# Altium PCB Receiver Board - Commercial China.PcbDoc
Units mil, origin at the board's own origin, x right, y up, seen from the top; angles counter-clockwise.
Board outline 2000 x 1000 mil, 2 copper layers (Top Layer, Bottom Layer); 23 components, 21 nets, 121 pads, 26 vias.
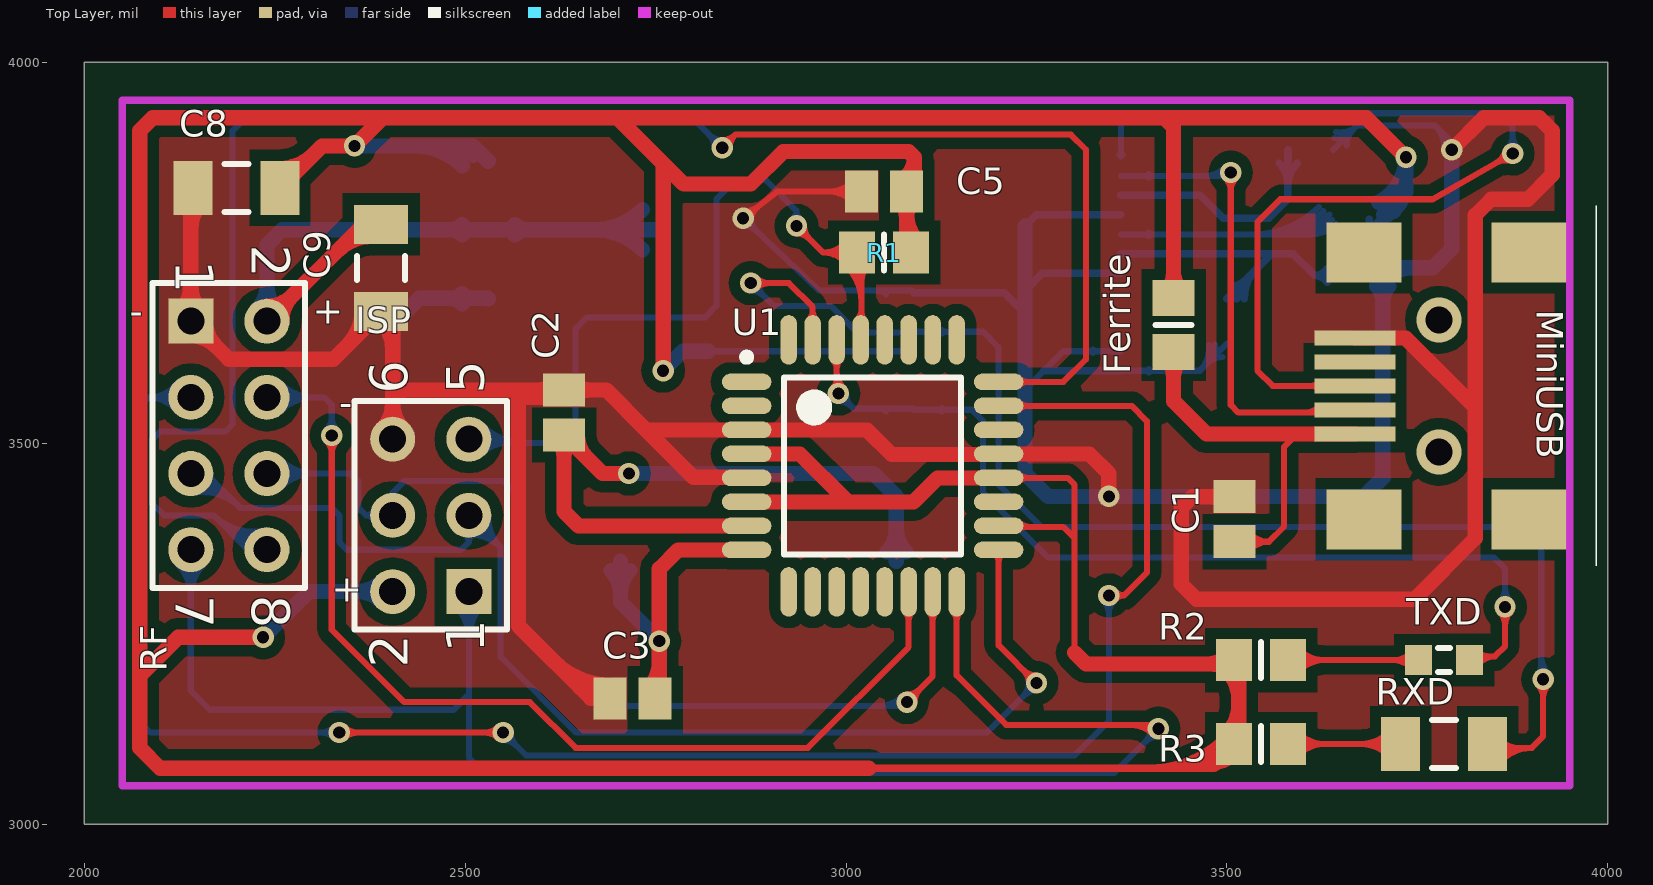
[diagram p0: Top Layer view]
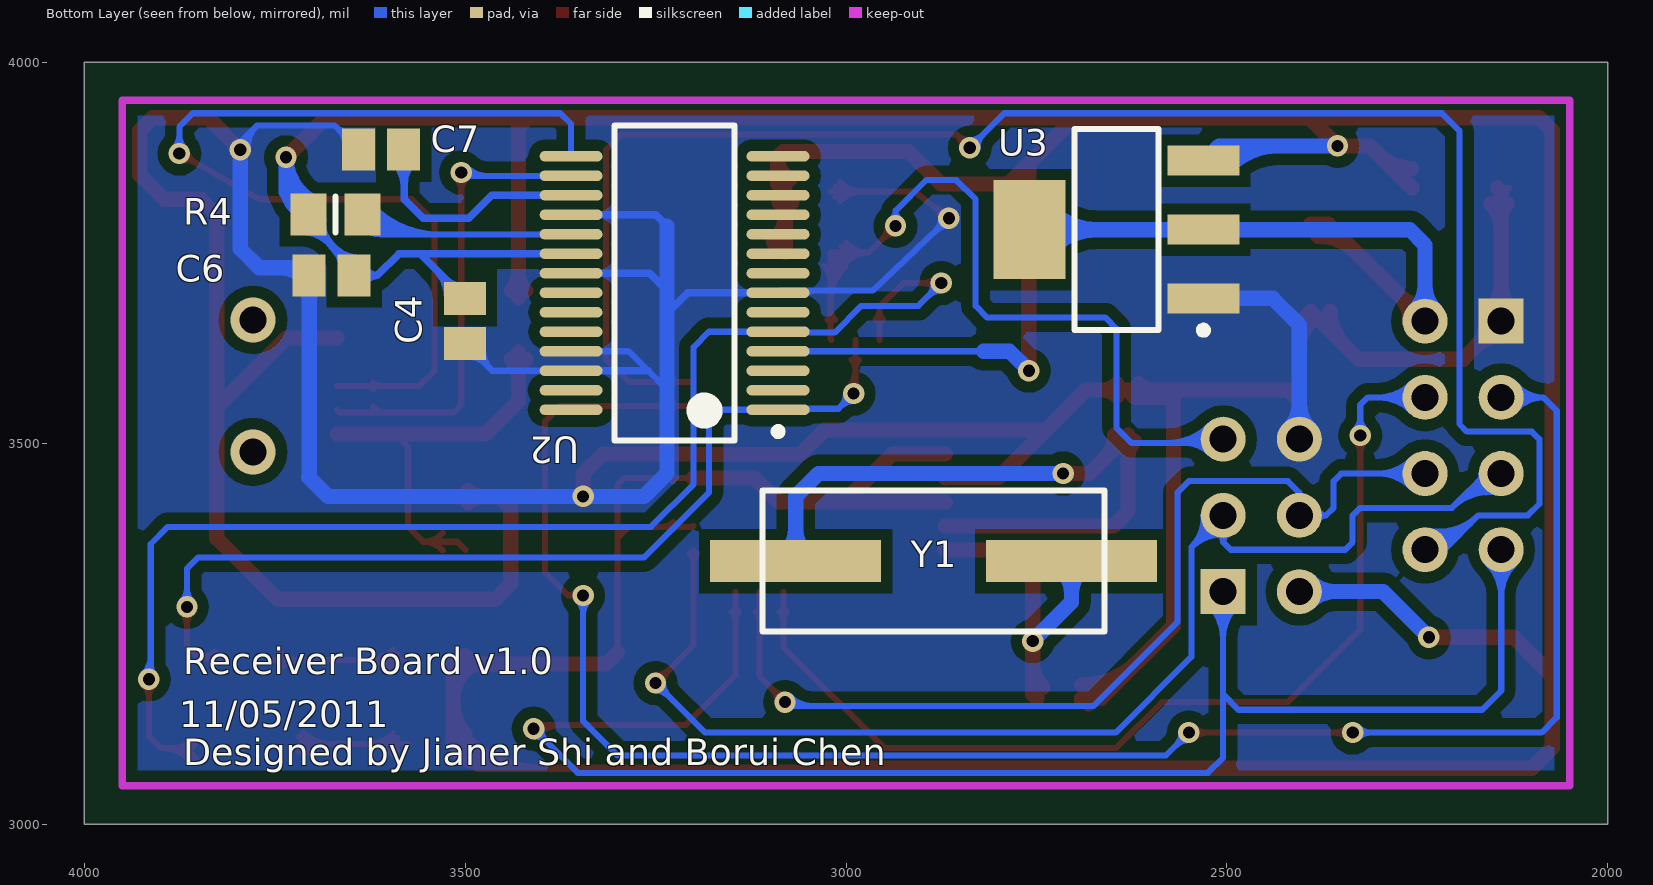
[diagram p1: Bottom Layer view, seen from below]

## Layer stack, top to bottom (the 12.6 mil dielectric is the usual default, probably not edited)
Top Layer: signal copper 1.4
Dielectric: dielectric 12.6, FR-4, Dk 4.8
Bottom Layer: signal copper 1.4

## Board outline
2000,3000 4000,3000 4000,4000 2000,4000

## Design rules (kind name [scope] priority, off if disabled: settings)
Clearance "Polygon Clearance" [InPolygon] p1: gap=15
Clearance [All] p2: gap=8.1
HoleSize [All] p1: absolutevalues=TRUE maxlimit=100 minlimit=16 maxpercent=80.000 minpercent=20.000
MinimumAnnularRing [All] p1: minimumring=6
PolygonConnect [All] p1: connectstyle=Direct reliefconductorwidth=10 reliefentries=4 polygonreliefangle="90 Angle"
RoutingVias [All] p1: holewidth=16 width=28 viastyle="Through Hole" minholewidth=16 minwidth=27 maxholewidth=16 maxwidth=35
SilkscreenOverComponentPads [All] p1: minsilkscreentomaskgap=10
SolderMaskExpansion [All] p1: expansion=4
Width [All] p1: maxlimit=50 minlimit=8 preferedwidth=8
26 further rules are at their usual default settings.

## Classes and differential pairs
component class "5V to 3.3V": C8 C9 U3
component class "2.4ghz Receiver Board": C1 C2 C3 C4 C5 C6 C7 Ferrite ISP MiniUSB R1 R2 R3 R4 RF RXD TXD U1 U2 Y1

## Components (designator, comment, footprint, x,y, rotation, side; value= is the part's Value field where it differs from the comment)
C1 "Cap Semi" CAPC2012L 3510,3400 r90 top
C2 "Cap Semi" CAPC2012L 2630,3540 r270 top
C3 "Cap Semi" CAPC2012L 2720,3165 r0 top
C4 "Cap Semi" CAPC2012L 3500,3660 r90 bottom
C5 "Cap Semi" CAPC2012L 3050,3830 r0 top
C6 "Cap Semi" CAPC2012L 3675,3720 r180 bottom
C7 "Cap Semi" CAPC2012L 3610,3885 r0 bottom
C8 "Cap Pol3 TANT" capc3216n 2200,3835 r180 top
C9 "Cap Pol3 TANT" capc3216n 2390,3730 r270 top
Ferrite "Ferrite Bead 1A" RESC2012N 3430,3655 r90 top
ISP "Header 3X2" HDR2X3 2505,3305 r90 top
MiniUSB "Mini USB" "MINI USB" 3985,3575 r180 top
R1 "Res3" RESC2012N 3050,3750 r0 top
R2 "Res3" RESC2012N 3545,3215 r0 top
R3 "Res3" RESC2012N 3545,3105 r0 top
R4 "Res3" RESC2012N 3670,3800 r180 bottom
RF "Header 4X2" HDR2X4 2140,3660 r270 top (schematic designator "RF Board")
RXD "LED2" RESC3216N 3785,3105 r0 top
TXD "LED2" RESC1608N 3785,3215 r0 top
U1 "ATmega8L-8AI" 32A_N 3035,3470 r0 top
U2 "FT232RL-Reel" SSOP-28_N 3225,3710 r0 bottom
U3 "LM1117MPX-3.3" MP04A_N 2645,3780 r0 bottom
Y1 "XTAL 8Mhz" "HC-49U - SMD" 2885,3345 r180 bottom

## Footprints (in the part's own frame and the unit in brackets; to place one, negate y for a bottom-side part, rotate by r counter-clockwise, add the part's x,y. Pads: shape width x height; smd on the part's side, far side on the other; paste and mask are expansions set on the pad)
32A_N [mm] "Thin QFP, 32-Leads, Body 7x7mm, Pitch 0.8mm, IPC Medium Density"
  oval 1.65x0.55 smd: 1(-4.2,2.8) 2(-4.2,2) 3(-4.2,1.2) 4(-4.2,0.4) 5(-4.2,-0.4) 6(-4.2,-1.2) 7(-4.2,-2) 8(-4.2,-2.8) 17(4.2,-2.8) 18(4.2,-2) 19(4.2,-1.2) 20(4.2,-0.4) 21(4.2,0.4) 22(4.2,1.2) 23(4.2,2) 24(4.2,2.8)
  oval 0.55x1.65 smd: 9(-2.8,-4.2) 10(-2,-4.2) 11(-1.2,-4.2) 12(-0.4,-4.2) 13(0.4,-4.2) 14(1.2,-4.2) 15(2,-4.2) 16(2.8,-4.2) 25(2.8,4.2) 26(2,4.2) 27(1.2,4.2) 28(0.4,4.2) 29(-0.4,4.2) 30(-1.2,4.2) 31(-2,4.2) 32(-2.8,4.2)
  silkscreen extent -4.32,-2.95 2.95,3.75, body extent -3.5,-3.5 3.5,3.5, height 1.2
CAPC2012L [mm] "Chip Capacitor, Body 2.0x1.3mm, IPC High Density"
  rect 1.1x1.4 smd: 1(-0.75,0) 2(0.75,0)
  body extent -1.1,-0.72 1.1,0.72, height 1.1
capc3216n [mm] "Chip Capacitor, Body 3.2x1.6mm, IPC Medium Density"
  rect 1.3x1.8 smd: 1(-1.45,0) 2(1.45,0)
  silkscreen extent -0.4,-0.8 0.4,0.8, body extent -1.7,-0.9 1.7,0.9, height 1.35
"HC-49U - SMD" [mm] "Quartz Crystal, Thru-Hole; 2 Leads; Body 11.35 x 4.65 x 13.46 mm (LxWxH max)"
  rect 5.7x1.4 smd: 1(-4.6,0) 2(4.6,0)
  silkscreen extent -5.7,-2.35 5.7,2.35
HDR2X3 [mm] "Connector; Header; 3x2 Position"
  rect 1.5x1.5 hole 0.9: 1(0,0)
  round 1.5 hole 0.9: 2(0,2.54) 3(2.54,0) 4(2.54,2.54) 5(5.08,0) 6(5.08,2.54)
  silkscreen extent -1.27,-1.27 6.35,3.81
HDR2X4 [mm] "Connector; Header; 4x2 Position"
  rect 1.5x1.5 hole 0.9: 1(0,0)
  round 1.5 hole 0.9: 2(0,2.54) 3(2.54,0) 4(2.54,2.54) 5(5.08,0) 6(5.08,2.54) 7(7.62,0) 8(7.62,2.54)
  silkscreen extent -1.27,-1.27 8.89,3.81
"MINI USB" [mm] "Digikey http://search.digikey.com/us/en/products/1734035-2/A31727CT-ND/773789"
  rect 2.7x0.5 smd: 1(8.05,1.6) 2(8.05,0.8) 3(8.05,0) 4(8.05,-0.8) 5(8.05,-1.6)
  rect 2.5x2 smd: NC(2.25,4.45) NC(2.25,-4.45) NC(7.75,-4.45) NC(7.75,4.45)
  silkscreen extent 0,-6 0,6
MP04A_N [mm] "SOT223, 4-Leads, Body 6.5x3.5mm, Pitch 2.3mm, Lead Span 7mm, IPC Medium Density"
  rect 2.4x1 smd: 1(-2.9,2.3) 2(-2.9,0) 3(-2.9,-2.3)
  rect 2.4x3.3 smd: 4(2.9,0)
  silkscreen extent -3.02,-3.35 1.4,3.47, body extent -1.85,-3.35 1.85,3.35, height 1.8
RESC1608N [mm] "Chip Resistor, Body 1.6x0.8mm, IPC Medium Density"
  rect 0.9x1 smd: 1(-0.85,0) 2(0.85,0)
  silkscreen extent -0.2,-0.4 0.2,0.4, body extent -0.85,-0.48 0.85,0.48, height 0.6
RESC2012N [mm] "Chip Resistor, Body 2.0x1.3mm, IPC Medium Density"
  rect 1.2x1.4 smd: 1(-0.9,0) 2(0.9,0)
  silkscreen extent 0,-0.6 0,0.6, body extent -1.07,-0.7 1.07,0.7, height 0.65
RESC3216N [mm] "Chip Resistor, Body 3.2x1.6mm, IPC Medium Density"
  rect 1.3x1.8 smd: 1(-1.45,0) 2(1.45,0)
  silkscreen extent -0.4,-0.8 0.4,0.8, body extent -1.68,-0.87 1.68,0.87, height 0.71
SSOP-28_N [mm] "SOP, 28-Leads, Body 10.2x5.3mm, Pitch 0.65mm, IPC Medium Density"
  oval 2.1x0.35 smd: 1(-3.45,4.225) 2(-3.45,3.575) 3(-3.45,2.925) 4(-3.45,2.275) 5(-3.45,1.625) 6(-3.45,0.975) 7(-3.45,0.325) 8(-3.45,-0.325) 9(-3.45,-0.975) 10(-3.45,-1.625) 11(-3.45,-2.275) 12(-3.45,-2.925) 13(-3.45,-3.575) 14(-3.45,-4.225) 15(3.45,-4.225) 16(3.45,-3.575) 17(3.45,-2.925) 18(3.45,-2.275) 19(3.45,-1.625) 20(3.45,-0.975) 21(3.45,-0.325) 22(3.45,0.325) 23(3.45,0.975) 24(3.45,1.625) 25(3.45,2.275) 26(3.45,2.925) 27(3.45,3.575) 28(3.45,4.225)
  silkscreen extent -3.57,-5.25 2,5.25, body extent -2.8,-5.25 2.8,5.25, height 2

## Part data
C1 C2 C3 C4 C5 C6 C7: "Capacitor (Semiconductor SIM Model)"
C8 C9: library part "Cap Pol3", "Polarized Capacitor (Surface Mount)"
Ferrite: library part "Ferrite Bead"
ISP: "Header, 3-Pin, Dual row"
R1 R2 R3 R4: "Resistor"
RF: "Header, 4-Pin, Dual row"
RXD TXD: "Typical RED, GREEN, YELLOW, AMBER GaAs LED"
U1: "8-Bit AVR Microcontroller with 8K Bytes of In-System Programmable Flash Memory"
U2: "USB UART Asynchronous Serial Data Transfer Chip, SSOP-28, Tape and Reel"
U3: "800mA Low-Dropout Linear Regulator, 4-pin SOT-223"
Y1: library part XTAL, "Crystal Oscillator"

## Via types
v1: diameter 28, hole 16, Top Layer to Bottom Layer, 24 vias
v2: diameter 59.06, hole 35.43, Top Layer to Bottom Layer, 2 vias

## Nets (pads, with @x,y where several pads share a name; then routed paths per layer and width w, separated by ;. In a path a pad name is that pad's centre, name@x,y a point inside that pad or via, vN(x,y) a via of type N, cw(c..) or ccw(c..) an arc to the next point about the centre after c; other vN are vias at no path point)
3.3VCC: C9.1 RF.2 U3.2 U3.4 | length 1247.2
  Top Layer w20: RF.2 2367.09,3787.09 C9.1 ; RF.2@2240,3679.53 ccw(c2240,3726.67) 2273.34,3693.34 ccw(c2306.67,3660) RF.2@2259.53,3660 ; 2331.23,3751.23 cw(c2380.16,3702.3) C9.1@2380.16,3771.5
  Bottom Layer w20: RF.2@2226.19,3673.81 ccw(c2192.86,3707.14) 2240,3707.14 ccw(c2287.14,3707.14) RF.2@2253.81,3673.81 ; RF.2 2240,3760 2260,3780 U3.2 U3.4 ; U3.2@2496.42,3773.15 ccw(c2479.89,3756.62) 2479.89,3780 ccw(c2479.89,3803.38) U3.2@2496.42,3786.85 ; U3.2@2565.23,3773.15 cw(c2581.77,3756.62) 2581.77,3780 cw(c2581.77,3803.38) U3.2@2565.23,3786.85 ; U3.4@2732.84,3753.66 ccw(c2669.26,3690.08) 2669.26,3780 ccw(c2669.26,3869.92) U3.4@2732.84,3806.34
5VCC: C4.2 C5.2 C6.2 C8.1 Ferrite.2 ISP.2 R1.2 R2.1 R3.1 R4.1 U1.4 U1.6 U1.18 U1.20 U2.4 U2.20 U3.3 | length 9447.2
  Top Layer w8: U1.18 3201.61,3390 3285,3390 3300,3375 ; U1.20 3290.75,3454.25 3300,3445 3300,3375 ; U1.18@3226.84,3386.43 cw(c3235.45,3377.82) 3235.45,3390 ; U1.18@3226.84,3396.09 ccw(c3241.53,3410.78) 3241.53,3390 ; U1.20@3226.84,3449.42 cw(c3238.49,3437.77) 3238.49,3454.25 cw(c3238.49,3470.73) U1.20@3226.84,3459.08 ; 3300,3225 3300,3375 ; R2.1@3510.47,3210 R2.1@3515.47,3215
  Top Layer w10: 3030,3073.1 3483.57,3073.1 ; 3345,3926.9 3350,3931.9 ; 3397.1,3073.1 ccw(c3397.1,3213.53) R3.1@3496.4,3114.23 ; 3421.24,3073.1 ccw(c3421.24,3189.39) R3.1@3503.47,3107.16 ; 3445.38,3073.1 ccw(c3445.38,3165.25) R3.1@3510.54,3100.09 ; 3469.53,3073.1 ccw(c3469.53,3141.1) R3.1@3517.61,3093.02 ; R3.1@3491.25,3097.71 cw(c3463.95,3092.72) 3483.57,3073.1 ; R3.1@3508.39,3082.48 ccw(c3506.37,3050.31) 3483.57,3073.1 ; R3.1@3515.47,3105 3483.57,3073.1
  Top Layer w20: v1(2235,3245) 2123.1,3245 2073.1,3195 ; C8.1 2312.09,3890 v1(2355,3890) 2391.9,3926.9 ; C8.1@2257.09,3860.43 ccw(c2257.09,3921.83) 2300.5,3878.42 ; v1(2760,3595) 2760,3866.9 ; U1.6 3088.5,3422.76 3120,3454.25 U1.20 ; U1.4 2939.25,3485.75 3000,3425 ; 3030,3073.1 2100,3073.1 2073.1,3100 2073.1,3195 ; C5.2@3071.29,3815.85 cw(c3051.39,3795.96) 3079.53,3795.96 cw(c3107.66,3795.96) C5.2@3087.77,3815.85 ; C5.2@3073.53,3845.9 ccw(c3056.05,3875) 3090,3875 ; R1.2@3079.53,3750 C5.2 3090,3840.47 3090,3875 ; 3079.53,3801.08 ccw(c3132.58,3801.08) R1.2@3095.07,3763.57 ; 3300,3225 3315,3210 R2.1@3510.47,3210 ; Ferrite.2@3420.37,3700.07 ccw(c3397.11,3723.32) 3430,3723.32 ccw(c3462.89,3723.32) Ferrite.2@3439.63,3700.07 ; Ferrite.2 3430,3875 3430,3915 3418.1,3926.9 ; 3474.11,3210 ccw(c3474.11,3246.52) R2.1@3499.93,3220.7 ; 3479.25,3210 cw(c3479.25,3180.74) 3499.93,3201.43 cw(c3462.42,3163.92) 3515.47,3163.92 ; R3.1@3499.93,3118.57 ccw(c3462.42,3156.08) 3515.47,3156.08 ; R3.1@3515.47,3105 R2.1@3515.47,3215 ; v1(3735,3875) 3683.1,3926.9 3418.1,3926.9 ; 2073.1,3195 2073.1,3910 2090,3926.9 2391.9,3926.9 ; 2391.9,3926.9 2700,3926.9 ; 2700,3926.9 2760,3866.9 ; 2700,3926.9 3345,3926.9 3418.1,3926.9 ; 2760,3866.9 2786.9,3840 2875,3840 2917.7,3882.7 3082.3,3882.7 3090,3875
  Bottom Layer w8: 2819.57,3620.43 U2.4 ; U2.4@3052.68,3618.39 ccw(c3047.75,3613.46) 3047.75,3620.43 ccw(c3047.75,3627.41) U2.4@3052.68,3622.48
  Bottom Layer w10: U2.20 3558.86,3748.39 ; C4.2 3558.86,3748.39 ; C4.2@3505.91,3706.18 ccw(c3505.91,3732.13) 3524.25,3713.78 ; C4.2@3512.56,3689.53 cw(c3542.88,3689.53) C4.2@3521.44,3710.97 ; C4.2@3522.56,3689.53 cw(c3577.02,3689.53) 3538.51,3728.04 ; C6.2@3631.46,3711.01 ccw(c3615,3700.45) 3615,3720 ; C6.2@3631.46,3728.99 cw(c3615,3739.55) 3615,3720 ; C6.2@3643.11,3742.39 ccw(c3635.7,3794.16) 3677.55,3762.8 ; C6.2@3644.53,3732.49 ccw(c3640.54,3760.36) C6.2@3663.07,3743.48 ; C6.2@3645.47,3740.04 C6.2 ; C6.2@3661.96,3728.27 cw(c3689.79,3732.25) 3667.29,3749.11 ; 3673.16,3756.94 cw(c3715.59,3725.15) R4.1@3708.07,3777.63 ; 3680,3766.07 ccw(c3650.48,3788.19) R4.1@3687,3793.42 ; R4.1@3687.64,3776.26 cw(c3710.75,3758.94) R4.1@3706.66,3787.53 ; R4.1 C6.2 ; 3558.86,3748.39 3586.61,3748.39 3615,3720 ; 3615,3720 C6.2
  Bottom Layer w20: v1(2235,3245) 2295,3305 ISP.2 ; v1(2355,3890) 2510.28,3890 2530.28,3870 U3.3 ; ISP.2@2391.19,3291.19 ccw(c2357.86,3257.86) 2357.86,3305 ccw(c2357.86,3352.14) ISP.2@2391.19,3318.81 ; 2432.93,3890 cw(c2432.93,3800.22) U3.3@2496.42,3863.7 ; 2481.22,3890 cw(c2481.22,3848.5) U3.3@2510.56,3877.85 ; v1(2760,3595) 2785.43,3620.43 2819.57,3620.43 ; R4.1@3699.16,3816.03 ccw(c3668.57,3875) v1(3735,3875) 3735,3829.57 ; R4.1 3735,3829.57 ; R4.1@3705.58,3817.56 ccw(c3706.01,3858.56) 3735,3829.57 ; R4.1@3708.37,3798.28 ccw(c3685.64,3842.09) 3735,3842.09 ; R4.1@3719.06,3803.94 cw(c3742.44,3803.94) R4.1@3725.9,3820.47
\R\E\S\E\T\: ISP.5 R1.1 U1.29 | length 1514
  Top Layer w8: v1@2935,3775 cw(c2935,3750.86) 2952.07,3767.93 cw(c2969.14,3785) v1@2945,3785 ; v1(2935,3785) 2970,3750 ; R1.1@3000.09,3736.75 ccw(c2970,3709.2) 2970,3750 ; R1.1@3000.09,3763.25 cw(c2970,3790.8) 2970,3750 ; R1.1@3000.69,3732.19 cw(c2952.94,3684.43) 3020.47,3684.43 ; R1.1@3005.99,3742.15 ccw(c2988.17,3725.84) 2988.17,3750 ccw(c2988.17,3774.16) R1.1@3005.99,3757.85 ; R1.1@3006.35,3737.85 cw(c2972.25,3703.75) 3020.47,3703.75 ; R1.1@3012.01,3743.5 cw(c2991.57,3723.06) R1.1@3020.47,3723.06 ; U1.29@3014.42,3661.84 ccw(c2999.82,3676.44) 3020.47,3676.44 ; U1.29 3020.47,3636.57 3020.47,3750 2970,3750 ; 3020.47,3670.54 ccw(c3032.79,3670.54) U1.29@3024.08,3661.84 ; 3020.47,3712.95 cw(c3047.68,3712.95) R1.1@3028.44,3732.19
  Bottom Layer w8: ISP.5 2510,3500 2625,3500 2645,3520 2645,3650 2660,3665 2815,3665 2830,3680 2830,3820 2855,3845 2895,3845 2935,3805 ; ISP.5@2511.74,3511.74 ccw(c2540.07,3540.07) 2540.07,3500 ; ISP.5@2517.39,3492.61 cw(c2535.24,3474.76) 2535.24,3500 ; ISP.5@2517.39,3517.39 ccw(c2559.39,3559.39) 2559.39,3500 ; ISP.5@2523.05,3486.95 cw(c2554.56,3455.44) 2554.56,3500 ; ISP.5@2523.05,3523.05 ccw(c2578.7,3578.7) 2578.7,3500 ; v1@2929,3793 ccw(c2920,3805) 2935,3805 ; v1(2935,3785) 2935,3805 ; v1@2941,3793 cw(c2950,3805) 2935,3805
CE: RF.3 U1.23 | length 2808.3
  Top Layer w8: v1(2335,3120) v1(2550,3120) ; v1@2342.07,3112.93 cw(c2359.14,3095.86) 2359.14,3120 cw(c2359.14,3144.14) v1@2342.07,3127.07 ; v1@2542.93,3112.93 ccw(c2525.86,3095.86) 2525.86,3120 ccw(c2525.86,3144.14) v1@2542.93,3127.07 ; U1.23 3375,3548.74 3395,3528.74 3395,3330 3365,3300 ; U1.23@3226.84,3543.91 cw(c3238.49,3532.26) 3238.49,3548.74 cw(c3238.49,3565.22) U1.23@3226.84,3553.57 ; v1(3345,3300) 3365,3300 ; v1@3353,3294 cw(c3365,3285) 3365,3300 ; v1@3353,3306 ccw(c3365,3315) 3365,3300
  Bottom Layer w8: RF.3@2120.5,3543.52 ccw(c2085,3513.52) 2085,3560 ; RF.3@2120.5,3576.48 cw(c2085,3606.48) 2085,3560 ; RF.3@2126.61,3548.69 ccw(c2102.24,3528.09) 2102.24,3560 ccw(c2102.24,3591.91) RF.3@2126.61,3571.31 ; RF.3 2085,3560 ; v1@2327.93,3112.93 ccw(c2310.86,3095.86) 2310.86,3120 ccw(c2310.86,3144.14) v1@2327.93,3127.07 ; v1(2335,3120) 2087.1,3120 2067.1,3140 2067.1,3542.1 2085,3560 ; v1@2550,3110 cw(c2550,3085.86) 2567.07,3102.93 cw(c2584.14,3120) v1@2560,3120 ; v1(2550,3120) 2580,3090 3300,3090 3345,3135 v1(3345,3300) ; v1@3337.93,3292.93 cw(c3320.86,3275.86) 3345,3275.86 cw(c3369.14,3275.86) v1@3352.07,3292.93
CSN: RF.4 U1.14 | length 1597.8
  Top Layer w8: v1@2317.93,3502.93 cw(c2300.86,3485.86) 2325,3485.86 cw(c2349.14,3485.86) v1@2332.07,3502.93 ; v1(2325,3510) 2325,3255 2420,3160 2585,3160 2645,3100 2950,3100 3082.24,3232.24 U1.14 ; U1.14@3077.42,3278.16 cw(c3065.76,3266.51) 3082.24,3266.51 cw(c3098.73,3266.51) U1.14@3087.07,3278.16
  Bottom Layer w8: RF.4 2315,3560 2325,3550 v1(2325,3510) ; RF.4@2252.39,3547.61 cw(c2282.32,3517.68) 2282.32,3560 cw(c2282.32,3602.32) RF.4@2252.39,3572.39 ; RF.4@2258.05,3541.95 cw(c2301.63,3498.37) 2301.63,3560 cw(c2301.63,3621.63) RF.4@2258.05,3578.05 ; v1@2317.93,3517.07 ccw(c2300.86,3534.14) 2325,3534.14 ccw(c2349.14,3534.14) v1@2332.07,3517.07
GND: C1.2 C2.1 C3.1 C4.1 C5.1 C6.1 C7.2 C8.2 C9.2 ISP.6 MiniUSB.5 RF.1 U1.3 U1.5 U1.21 U2.7 U2.18 U2.21 U2.25 U2.26 U3.1 | length 8316.6
  Top Layer w8: C8.2@2130,3835 C8.2@2144.88,3835 ; v1(2865,3795) 2910,3830 C5.1 ; v1@2866.24,3804.92 ccw(c2869.23,3828.88) 2884.06,3809.82 ccw(c2898.88,3790.77) v1@2874.92,3793.76 ; C5.1@3007.99,3817.52 ccw(c2977.85,3787.38) 2977.85,3830 ccw(c2977.85,3872.62) C5.1@3007.99,3842.48 ; C5.1@3013.65,3823.17 ccw(c2997.17,3806.69) 2997.17,3830 ccw(c2997.17,3853.31) C5.1@3013.65,3836.83
  Top Layer w20: RF.1@2126.19,3673.81 ccw(c2092.86,3707.14) 2140,3707.14 ccw(c2187.14,3707.14) RF.1@2153.81,3673.81 ; C8.2@2131.89,3814.13 cw(c2112.31,3794.55) 2140,3794.55 ; RF.1@2140,3640.47 cw(c2140,3593.33) 2173.34,3626.66 cw(c2206.67,3660) RF.1@2159.53,3660 ; 2140,3780.49 cw(c2187.59,3780.49) C8.2@2153.94,3814.13 ; C8.2@2144.88,3835 2140,3830.12 RF.1 2190,3610 2327.09,3610 C9.2 2405,3657.91 2405,3555 ; 2346.58,3629.5 ccw(c2303.17,3672.91) C9.2@2364.57,3672.91 ; C9.2@2388.82,3661.89 cw(c2349.75,3622.82) 2405,3622.82 ; ISP.6@2391.19,3518.81 ccw(c2357.86,3552.14) 2405,3552.14 ccw(c2452.14,3552.14) ISP.6@2418.81,3518.81 ; ISP.6 2405,3555 ; C9.2@2405,3647.73 cw(c2425.03,3647.73) C9.2@2410.87,3661.89 ; 2572.96,3560 ccw(c2572.96,3620.66) 2615.85,3577.77 cw(c2595.96,3597.66) 2595.96,3569.53 cw(c2595.96,3541.39) C2.1@2615.85,3561.29 ; 2617.01,3212.99 ccw(c2690.47,3286.45) C3.1@2690.47,3182.56 ; C2.1@2644.15,3561.29 cw(c2664.04,3541.39) 2664.04,3569.53 cw(c2664.04,3597.66) C2.1@2644.15,3577.77 ; 2651.16,3178.84 ccw(c2690.47,3218.16) C3.1@2690.47,3162.56 ; C3.1@2681.65,3157.38 ccw(c2665,3142.99) 2665,3165 ; C3.1@2681.65,3172.62 cw(c2665,3187.01) 2665,3165 ; C3.1 2665,3165 ; U1.5 2868.9,3455 2800,3455 2737.76,3517.24 ; v1(3345,3430) 3345,3460 3319.25,3485.75 U1.21 3199.61,3485 3060,3485 3027.76,3517.24 U1.3 2737.76,3517.24 ; C1.2@3495.85,3421.29 ccw(c3475.96,3401.39) 3475.96,3429.53 ccw(c3475.96,3457.66) C1.2@3495.85,3437.77 ; C1.2 3454.53,3429.53 3440,3415 3440,3315 3460,3295 3745.93,3295 3825.93,3375 3825.93,3546.63 ; MiniUSB.5 3734.57,3637.99 3825.93,3546.63 ; v1(3795,3885) 3836.9,3926.9 3910,3926.9 3926.9,3910 3926.9,3851.9 3895,3820 3846.9,3820 3825.93,3799.03 3825.93,3546.63 ; 2405,3555 2419.53,3569.53 C2.1 ; C2.1 2685.47,3569.53 2737.76,3517.24 ; C2.1 2620.47,3560 2570,3560 2570,3260 2665,3165
  Bottom Layer w8: v1(2865,3795) 2965,3700 U2.7@3086.38,3700 ; v1@2865.26,3785 cw(c2865.88,3760.87) 2882.5,3778.37 cw(c2899.13,3795.88) v1@2875,3795.26 ; 3041,3700 cw(c3041,3683.48) U2.7@3052.68,3695.16 ; 3235,3570 3259.84,3594.84 3285.43,3620.43 U2.25 U2.25@3360.39,3620 ; U2.25@3324.33,3618.39 ccw(c3319.4,3613.46) 3319.4,3620.43 ccw(c3319.4,3627.41) U2.25@3324.33,3622.48 ; U2.26 3464.37,3594.84 ; U2.26@3397.32,3592.8 cw(c3402.25,3587.87) 3402.25,3594.84 cw(c3402.25,3601.82) U2.26@3397.32,3596.89 ; 3474.04,3604.51 cw(c3494.09,3584.46) C4.1@3494.09,3612.82 ; 3476.35,3606.82 ccw(c3456.37,3626.79) C4.1@3484.49,3629.54 ; C4.1@3476.52,3628.76 cw(c3434.55,3624.66) 3464.37,3594.84 ; C4.1 3464.37,3594.84 ; C7.2 3671.33,3916.8 ; C7.2@3641.42,3900.37 ccw(c3645.62,3921.37) C7.2@3660.75,3906.23 ; C7.2@3642.99,3908.22 ccw(c3649.14,3938.99) 3671.33,3916.8 ; C7.2@3657.18,3890.91 cw(c3685.54,3890.91) 3665.49,3910.96 ; v1@3785.02,3885.61 ccw(c3744.49,3888.09) 3773.2,3916.8 ; 3785.76,3904.24 cw(c3768.16,3886.64) v1@3793,3885.12 ; v1(3795,3885) 3795,3895 3773.2,3916.8 ; 3671.33,3916.8 3773.2,3916.8
  Bottom Layer w10: U2.7 3207.8,3697.2 3235,3670 ; 3235,3700 3257.8,3722.8 U2.21 ; 3235,3785 3249.57,3799.57 U2.18 ; 3259.84,3594.84 U2.26
  Bottom Layer w20: ISP.6@2391.19,3518.81 ccw(c2357.86,3552.14) 2405,3552.14 ccw(c2452.14,3552.14) ISP.6@2418.81,3518.81 ; ISP.6@2400,3510 ISP.6 2405,3655 2440,3690 2530.28,3690 U3.1 ; 2478.56,3690 cw(c2478.56,3664.74) U3.1@2496.42,3682.6 ; 2481.22,3690 ccw(c2481.22,3711.5) U3.1@2496.42,3696.3 ; 3235,3785 3235,3700 3235,3670 3235,3570 3235,3460 3265,3430 v1(3345,3430) 3680,3430 3705,3455 3704.53,3455.47 C6.1 3714.53,3730 3770,3730 3795,3755 3795,3870 ; C6.1@3696.29,3705.85 cw(c3676.39,3685.96) 3704.53,3685.96 cw(c3732.66,3685.96) C6.1@3712.77,3705.85 ; C6.1@3712.77,3717.67 cw(c3742.55,3687.89) 3742.55,3730
IRQ: RF.8 U1.24 | length 2649.5
  Top Layer w8: v1(2837.5,3887.5) 2854.8,3904.8 3295.2,3904.8 3315,3885 3315,3610 3285.24,3580.24 U1.24 ; v1@2837.5,3897.5 ccw(c2837.5,3921.64) 2854.57,3904.57 ccw(c2871.64,3887.5) v1@2847.5,3887.5 ; U1.24@3226.84,3575.41 cw(c3238.49,3563.76) 3238.49,3580.24 cw(c3238.49,3596.72) U1.24@3226.84,3585.06
  Bottom Layer w8: 2180.65,3394.35 ccw(c2224.79,3438.49) RF.8@2236.67,3377.21 ; 2191.3,3383.7 ccw(c2228.25,3420.66) RF.8@2238.19,3369.35 ; 2201.94,3373.06 ccw(c2231.7,3402.82) RF.8@2239.71,3361.5 ; RF.8@2235.14,3385.06 cw(c2221.33,3456.33) 2170,3405 ; RF.8 2215,3360 2170,3405 ; v1@2827.5,3887.5 ccw(c2803.36,3887.5) 2820.43,3904.57 ccw(c2837.5,3921.64) v1@2837.5,3897.5 ; v1(2837.5,3887.5) 2792.1,3932.9 2217.9,3932.9 2195,3910 2195,3525 2185,3515 2100,3515 2090,3505 2090,3420 2105,3405 2170,3405
MISO: ISP.1 RF.7 U1.16 | length 2567.1
  Top Layer w8: U1.16@3140.41,3278.16 cw(c3128.76,3266.51) 3145.24,3266.51 cw(c3161.72,3266.51) U1.16@3150.06,3278.16 ; U1.16 3145.24,3195 3210.24,3130 3405,3130 v1(3410,3125) ; 3373.79,3130 cw(c3373.79,3088.79) v1@3402.93,3117.93 ; 3393.1,3130 cw(c3393.1,3108.1) v1@3408.59,3123.59
  Bottom Layer w8: RF.7@2121.95,3341.95 cw(c2078.37,3298.37) 2140,3298.37 cw(c2201.63,3298.37) RF.7@2158.05,3341.95 ; RF.7@2127.61,3347.61 cw(c2097.68,3317.68) 2140,3317.68 cw(c2182.32,3317.68) RF.7@2152.39,3347.61 ; RF.7 2140,3175 2165,3150 2485,3150 2505,3170 ; ISP.1@2486.95,3286.95 cw(c2443.37,3243.37) 2505,3243.37 cw(c2566.63,3243.37) ISP.1@2523.05,3286.95 ; ISP.1@2492.61,3292.61 cw(c2462.68,3262.68) 2505,3262.68 cw(c2547.32,3262.68) ISP.1@2517.39,3292.61 ; ISP.1 2505,3170 ; v1@3400,3125 cw(c3375.86,3125) 3392.93,3107.93 cw(c3410,3090.86) v1@3410,3115 ; v1(3410,3125) 3352.1,3067.1 2525,3067.1 2505,3087.1 2505,3170
MOSI: ISP.4 RF.6 U1.15 | length 1620.6
  Top Layer w8: v1(3080,3160) 3113.74,3193.74 U1.15 ; v1@3080,3170 ccw(c3080,3194.14) 3097.07,3177.07 ccw(c3114.14,3160) v1@3090,3160 ; U1.15@3108.91,3278.16 cw(c3097.26,3266.51) 3113.74,3266.51 cw(c3130.22,3266.51) U1.15@3118.57,3278.16
  Bottom Layer w8: RF.6 2350,3460 2360,3450 2360,3415 2370,3405 ; RF.6@2252.39,3447.61 cw(c2282.32,3417.68) 2282.32,3460 cw(c2282.32,3502.32) RF.6@2252.39,3472.39 ; RF.6@2258.05,3441.95 cw(c2301.63,3398.37) 2301.63,3460 cw(c2301.63,3521.63) RF.6@2258.05,3478.05 ; ISP.4@2380.69,3397.2 ccw(c2370,3393.77) 2370,3405 ; ISP.4@2380.69,3412.8 cw(c2370,3416.23) 2370,3405 ; ISP.4@2400.92,3430.2 ccw(c2400.14,3435) 2405,3435 ; ISP.4@2409.08,3430.2 cw(c2409.86,3435) 2405,3435 ; 3043.79,3155 ccw(c3043.79,3196.21) v1@3072.93,3167.07 ; 3063.1,3155 ccw(c3063.1,3176.9) v1@3078.59,3161.41 ; v1(3080,3160) 3075,3155 2675,3155 2565,3265 2565,3435 2550,3450 2420,3450 2405,3435 ; 2370,3405 ISP.4 2405,3435
NetC1_1: C1.1 Ferrite.1 MiniUSB.1 | length 647.2
  Top Layer w8: C1.1@3499.53,3360 C1.1 3555,3370.47 ; C1.1@3529.15,3358.8 cw(c3555,3336.01) 3555,3370.47 ; C1.1@3529.15,3382.15 ccw(c3555,3404.93) 3555,3370.47 ; 3592.01,3512.01 3575,3495 3575,3390.47 3555,3370.47
  Top Layer w20: Ferrite.1@3420.37,3609.93 cw(c3397.11,3586.68) 3430,3586.68 cw(c3462.89,3586.68) Ferrite.1@3439.63,3609.93 ; Ferrite.1 3430,3555 3472.99,3512.01 3592.01,3512.01 MiniUSB.1
NetC2_2: C2.2 U1.7 Y1.1 | length 1098.6
  Top Layer w20: C2.2@2621.76,3502.23 cw(c2601.87,3482.34) 2630,3482.34 cw(c2658.13,3482.34) C2.2@2638.24,3502.23 ; C2.2@2647.56,3510.47 ccw(c2689.95,3510.47) 2659.98,3480.5 ; v1(2715,3460) 2680.47,3460 2655.47,3485 ; U1.7 2648.74,3391.26 2630,3410 2630,3435 C2.2 2655.47,3485 ; 2655.47,3485 cw(c2675.48,3505.01) 2647.45,3508.88 ccw(c2675.48,3505.01) 2655.47,3485
  Bottom Layer w20: v1(2715,3460) 3036.1,3460 3066.1,3430 Y1.1 ; Y1.1@3053.69,3357.42 ccw(c3023.71,3387.39) 3066.1,3387.39 ccw(c3108.49,3387.39) Y1.1@3078.52,3357.42
NetC3_2: C3.2 U1.8 Y1.2 | length 526.7
  Top Layer w20: C3.2@2741.29,3179.15 ccw(c2708.18,3212.25) 2755,3212.25 ; C3.2 2755,3170.47 v1(2755,3240) 2755,3335 2779.76,3359.76 U1.8
  Bottom Layer w20: Y1.2@2691.48,3332.58 cw(c2661.51,3302.61) 2703.9,3302.61 cw(c2746.29,3302.61) Y1.2@2716.31,3332.58 ; Y1.2 2703.9,3291.1 v1(2755,3240)
NetC7_1: C7.1 U2.17 | length 383.9
  Bottom Layer w10: U2.17 3464.84,3825.16 3495,3795 3555,3795 3580,3820 3580,3884.53 C7.1 C7.1@3580.47,3871.5 ; C7.1@3568.7,3867.32 cw(c3541.41,3840.03) 3580,3840.03 ; 3580,3837.75 cw(c3621.82,3837.75) C7.1@3592.25,3867.32
NetR2_2: R2.2 TXD.1 | length 341.6
  Top Layer w8: R2.2 TXD.1 ; R2.2@3588.65,3206.78 cw(c3608.49,3186.94) 3608.49,3215 cw(c3608.49,3243.06) R2.2@3588.65,3223.22 ; R2.2@3594.31,3201.13 cw(c3627.8,3167.63) 3627.8,3215 cw(c3627.8,3262.37) R2.2@3594.31,3228.87 ; TXD.1@3741.84,3205.3 ccw(c3718.42,3181.89) 3718.42,3215 ccw(c3718.42,3248.11) TXD.1@3741.84,3224.7
NetR3_2: R3.2 RXD.1 | length 393.5
  Top Layer w8: R3.2@3574.53,3105 RXD.1@3716.1,3105 ; R3.2@3588.65,3096.78 cw(c3608.49,3076.94) 3608.49,3105 cw(c3608.49,3133.06) R3.2@3588.65,3113.22 ; R3.2@3594.31,3091.13 cw(c3627.8,3057.63) 3627.8,3105 cw(c3627.8,3152.37) R3.2@3594.31,3118.87 ; RXD.1@3712.65,3089.73 ccw(c3675.79,3052.88) 3675.79,3105 ccw(c3675.79,3157.12) RXD.1@3712.65,3120.27 ; RXD.1@3718.3,3095.39 ccw(c3695.1,3072.19) 3695.1,3105 ccw(c3695.1,3137.81) RXD.1@3718.3,3114.61
NetR4_2: R4.2 U2.19 | length 667.5
  Bottom Layer w8: U2.19 3608.54,3773.98 ; U2.19@3397.32,3771.93 cw(c3402.25,3767) 3402.25,3773.98 cw(c3402.25,3780.95) U2.19@3397.32,3776.02 ; 3533.87,3773.98 ccw(c3533.87,3896.76) R4.2@3620.69,3809.94 ; 3553.19,3773.98 ccw(c3553.19,3877.44) R4.2@3626.35,3804.28 ; 3572.5,3773.98 ccw(c3572.5,3858.13) R4.2@3632.01,3798.62 ; 3591.81,3773.98 ccw(c3591.81,3838.82) R4.2@3637.66,3792.97 ; R4.2@3611.13,3773.98 ccw(c3611.13,3819.5) R4.2@3643.32,3787.31 ; R4.2@3615.12,3793.44 cw(c3592.17,3790.35) 3608.54,3773.98 ; R4.2@3627.3,3777.84 ccw(c3620.85,3761.67) 3608.54,3773.98 ; R4.2 3608.54,3773.98
NetRXD_2: RXD.2 U1.31 U2.5 | length 2052.1
  Top Layer w8: v1(2875,3710) 2925,3710 2956.26,3678.74 U1.31 ; v1@2882.07,3702.93 cw(c2899.14,3685.86) 2899.14,3710 cw(c2899.14,3734.14) v1@2882.07,3717.07 ; U1.31@2951.43,3661.84 ccw(c2939.78,3673.49) 2956.26,3673.49 ccw(c2972.74,3673.49) U1.31@2961.09,3661.84 ; RXD.2@3852.35,3086.25 cw(c3882.47,3060.14) 3882.47,3100 ; RXD.2@3853.9,3105 3858.9,3100 3900,3100 ; RXD.2@3857.35,3110.42 ccw(c3882.52,3135.59) 3882.52,3100 ; RXD.2@3858.4,3081.01 cw(c3900,3044.94) 3900,3100 ; v1@3907.93,3182.93 cw(c3890.86,3165.86) 3915,3165.86 cw(c3939.14,3165.86) v1@3922.07,3182.93 ; v1(3915,3190) 3915,3115 3900,3100
  Bottom Layer w8: v1@2875,3700 cw(c2875,3675.86) 2892.07,3692.93 cw(c2909.14,3710) v1@2885,3710 ; v1(2875,3710) 2905,3680 2980,3680 3015,3645 3088.15,3645 U2.5 3180,3646.02 3200,3626.02 3200,3446.1 3256.1,3390 3890,3390 3912.5,3367.5 3912.5,3192.5 v1(3915,3190) ; 3045.28,3645 ccw(c3045.28,3655.47) U2.5@3052.68,3648.07 ; U2.5@3125.67,3643.98 cw(c3130.6,3639.05) 3130.6,3646.02 cw(c3130.6,3653) U2.5@3125.67,3648.07 ; v1@3907.93,3197.07 ccw(c3896.89,3208.11) 3912.5,3208.11 ; 3912.5,3220.18 ccw(c3945.18,3220.18) v1@3922.07,3197.07
NetTXD_2: TXD.2 U1.30 U2.1 | length 1493.6
  Top Layer w8: v1@2982.93,3572.07 ccw(c2971.28,3583.72) 2987.76,3583.72 ; U1.30@2982.93,3608.87 cw(c2971.27,3597.22) 2987.76,3597.22 cw(c3004.24,3597.22) U1.30@2992.58,3608.87 ; 2987.76,3594.56 ccw(c3019.56,3594.56) v1@2997.07,3572.07 ; U1.30 2987.76,3567.24 v1(2990,3565) ; TXD.2 3823.46,3220 3851.73,3220 ; TXD.2@3828.16,3226.67 ccw(c3844.26,3242.76) 3844.26,3220 ; TXD.2@3829.48,3208.8 cw(c3851.73,3192.3) 3851.73,3220 ; v1@3857.93,3277.93 cw(c3840.86,3260.86) 3865,3260.86 cw(c3889.14,3260.86) v1@3872.07,3277.93 ; v1(3865,3285) 3865,3233.27 3851.73,3220
  Bottom Layer w8: v1@2990,3555 cw(c2990,3530.86) 3007.07,3547.93 cw(c3024.14,3565) v1@3000,3565 ; v1(2990,3565) 3010,3545 3087.83,3545 U2.1 3165,3543.66 3180,3528.66 3180,3435 3265,3350 3850,3350 3865,3335 v1(3865,3285) ; 3044.52,3545 cw(c3044.52,3533.45) U2.1@3052.68,3541.62 ; U2.1@3125.67,3541.62 cw(c3130.6,3536.68) 3130.6,3543.66 cw(c3130.6,3550.64) U2.1@3125.67,3545.7 ; v1@3857.93,3292.07 ccw(c3840.86,3309.14) 3865,3309.14 ccw(c3889.14,3309.14) v1@3872.07,3292.07
SCK: ISP.3 RF.5 U1.17 | length 2130.1
  Top Layer w8: U1.17@3195.53,3354.94 cw(c3183.87,3343.28) 3200.35,3343.28 cw(c3216.84,3343.28) U1.17@3205.18,3354.94 ; U1.17 3200.35,3234.65 v1(3250,3185) ; v1@3240,3185 ccw(c3215.86,3185) 3232.93,3202.07 ccw(c3250,3219.14) v1@3250,3195
  Bottom Layer w8: RF.5 2160,3460 2205,3415 ; RF.5@2140.24,3458.49 cw(c2145.97,3422.52) 2171.72,3448.28 ; RF.5@2141.5,3450.59 cw(c2149.01,3403.38) 2182.82,3437.18 ; RF.5@2142.76,3442.69 cw(c2152.06,3384.25) 2193.91,3426.09 ; RF.5@2144.01,3434.79 cw(c2155.11,3365.11) 2205,3415 ; RF.5@2165.53,3460 ccw(c2178.87,3460) 2169.44,3450.56 ; ISP.3@2497.2,3380.69 cw(c2493.77,3370) 2505,3370 ; ISP.3@2505.58,3387.48 cw(c2506.82,3349.66) 2533.58,3376.42 cw(c2560.34,3403.18) ISP.3@2522.52,3404.42 ; ISP.3@2505.84,3379.49 cw(c2507.66,3324.4) 2546.63,3363.37 ; ISP.3@2512.8,3380.69 ccw(c2516.23,3370) 2505,3370 ; ISP.3@2530.51,3404.16 ccw(c2585.6,3402.34) 2546.63,3363.37 ; v1@3240,3185 cw(c3215.86,3185) 3232.93,3167.93 cw(c3250,3150.86) v1@3250,3175 ; v1(3250,3185) 3185,3120 2646.1,3120 2546.63,3219.47 2546.63,3363.37 ; 2205,3415 2325,3415 2335,3405 2335,3370 2345,3360 2495,3360 2505,3370 ; 2505,3370 ISP.3 2546.63,3363.37
USBDM: MiniUSB.2 U2.16 | length 742.1
  Top Layer w8: v1@3497.93,3847.93 cw(c3480.86,3830.86) 3505,3830.86 cw(c3529.14,3830.86) v1@3512.07,3847.93 ; v1(3505,3855) 3505,3550 3515,3540 3664.57,3540 MiniUSB.2 ; 3602.2,3540 ccw(c3602.2,3566.07) MiniUSB.2@3620.63,3547.64
  Bottom Layer w8: U2.16 3500.75,3850.75 v1(3505,3855) ; U2.16@3397.32,3848.7 cw(c3402.25,3843.77) 3402.25,3850.75 cw(c3402.25,3857.72) U2.16@3397.32,3852.79 ; 3470.59,3850.75 ccw(c3470.59,3889.41) v1@3497.93,3862.07 ; 3489.91,3850.75 ccw(c3489.91,3870.09) v1@3503.59,3856.41 ; 3491.12,3850.75 cw(c3491.12,3841.12) v1@3497.93,3847.93
USBDP: MiniUSB.3 U2.15 | length 1408.5
  Top Layer w8: MiniUSB.3@3620.63,3570.87 ccw(c3610.66,3560.89) 3610.66,3575 ccw(c3610.66,3589.11) MiniUSB.3@3620.63,3579.13 ; MiniUSB.3 3560,3575 3540,3595 3540,3790 3570,3820 3770,3820 v1(3875,3880) ; v1@3865.35,3882.63 cw(c3842.06,3888.98) 3854.04,3868.02 cw(c3866.02,3847.06) v1@3872.37,3870.35
  Bottom Layer w8: U2.15@3358.78,3878.38 ccw(c3353.85,3883.32) 3360.83,3883.32 ccw(c3367.8,3883.32) U2.15@3362.87,3878.38 ; U2.15 3360.83,3918.73 3375,3932.9 3857.1,3932.9 3875,3915 v1(3875,3880) ; v1@3867.93,3887.07 ccw(c3850.86,3904.14) 3875,3904.14 ccw(c3899.14,3904.14) v1@3882.07,3887.07
pads on no net: MiniUSB.4 MiniUSB.NC U1.1 U1.2 U1.9 U1.10 U1.11 U1.12 U1.13 U1.19 U1.22 U1.25 U1.26 U1.27 U1.28 U1.32 U2.2 U2.3 U2.6 U2.8 U2.9 U2.10 U2.11 U2.12 U2.13 U2.14 U2.22 U2.23 U2.24 U2.27 U2.28
copper on no net:
  other v2: 3778.31,3488.39 3778.31,3661.61

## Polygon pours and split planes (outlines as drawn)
GND on Top Layer "Top Layer-No Net" (solid, pour order 2): 2025,3975 3975,3975 3975,3025 2025,3025
GND on Bottom Layer "bottom" (solid, pour order 4): 2025,3975 3975,3975 3975,3025 2025,3025

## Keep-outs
Keep-Out Layer:
  lines w10: 2050,3050 2050,3950 3950,3950 3950,3050 2050,3050

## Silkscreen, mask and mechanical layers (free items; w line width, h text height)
Top Overlay:
  text "-" at 2060,3645 h60
  text "+" at 2300,3645 h60
  text "-" at 2335,3525 h60
  text "+" at 2325,3280 h60
Bottom Overlay:
  text "Receiver Board v1.0" at 3870,3185 h60
  text "11/05/2011" at 3875,3115 h60
  text "Designed by Jianer Shi and Borui Chen" at 3870,3065 h60

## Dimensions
2050,3050 to 2050,3950 on Mechanical 1
2050,3050 to 3950,3050 on Mechanical 1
